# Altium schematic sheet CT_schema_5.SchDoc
size 326 x 334 mm
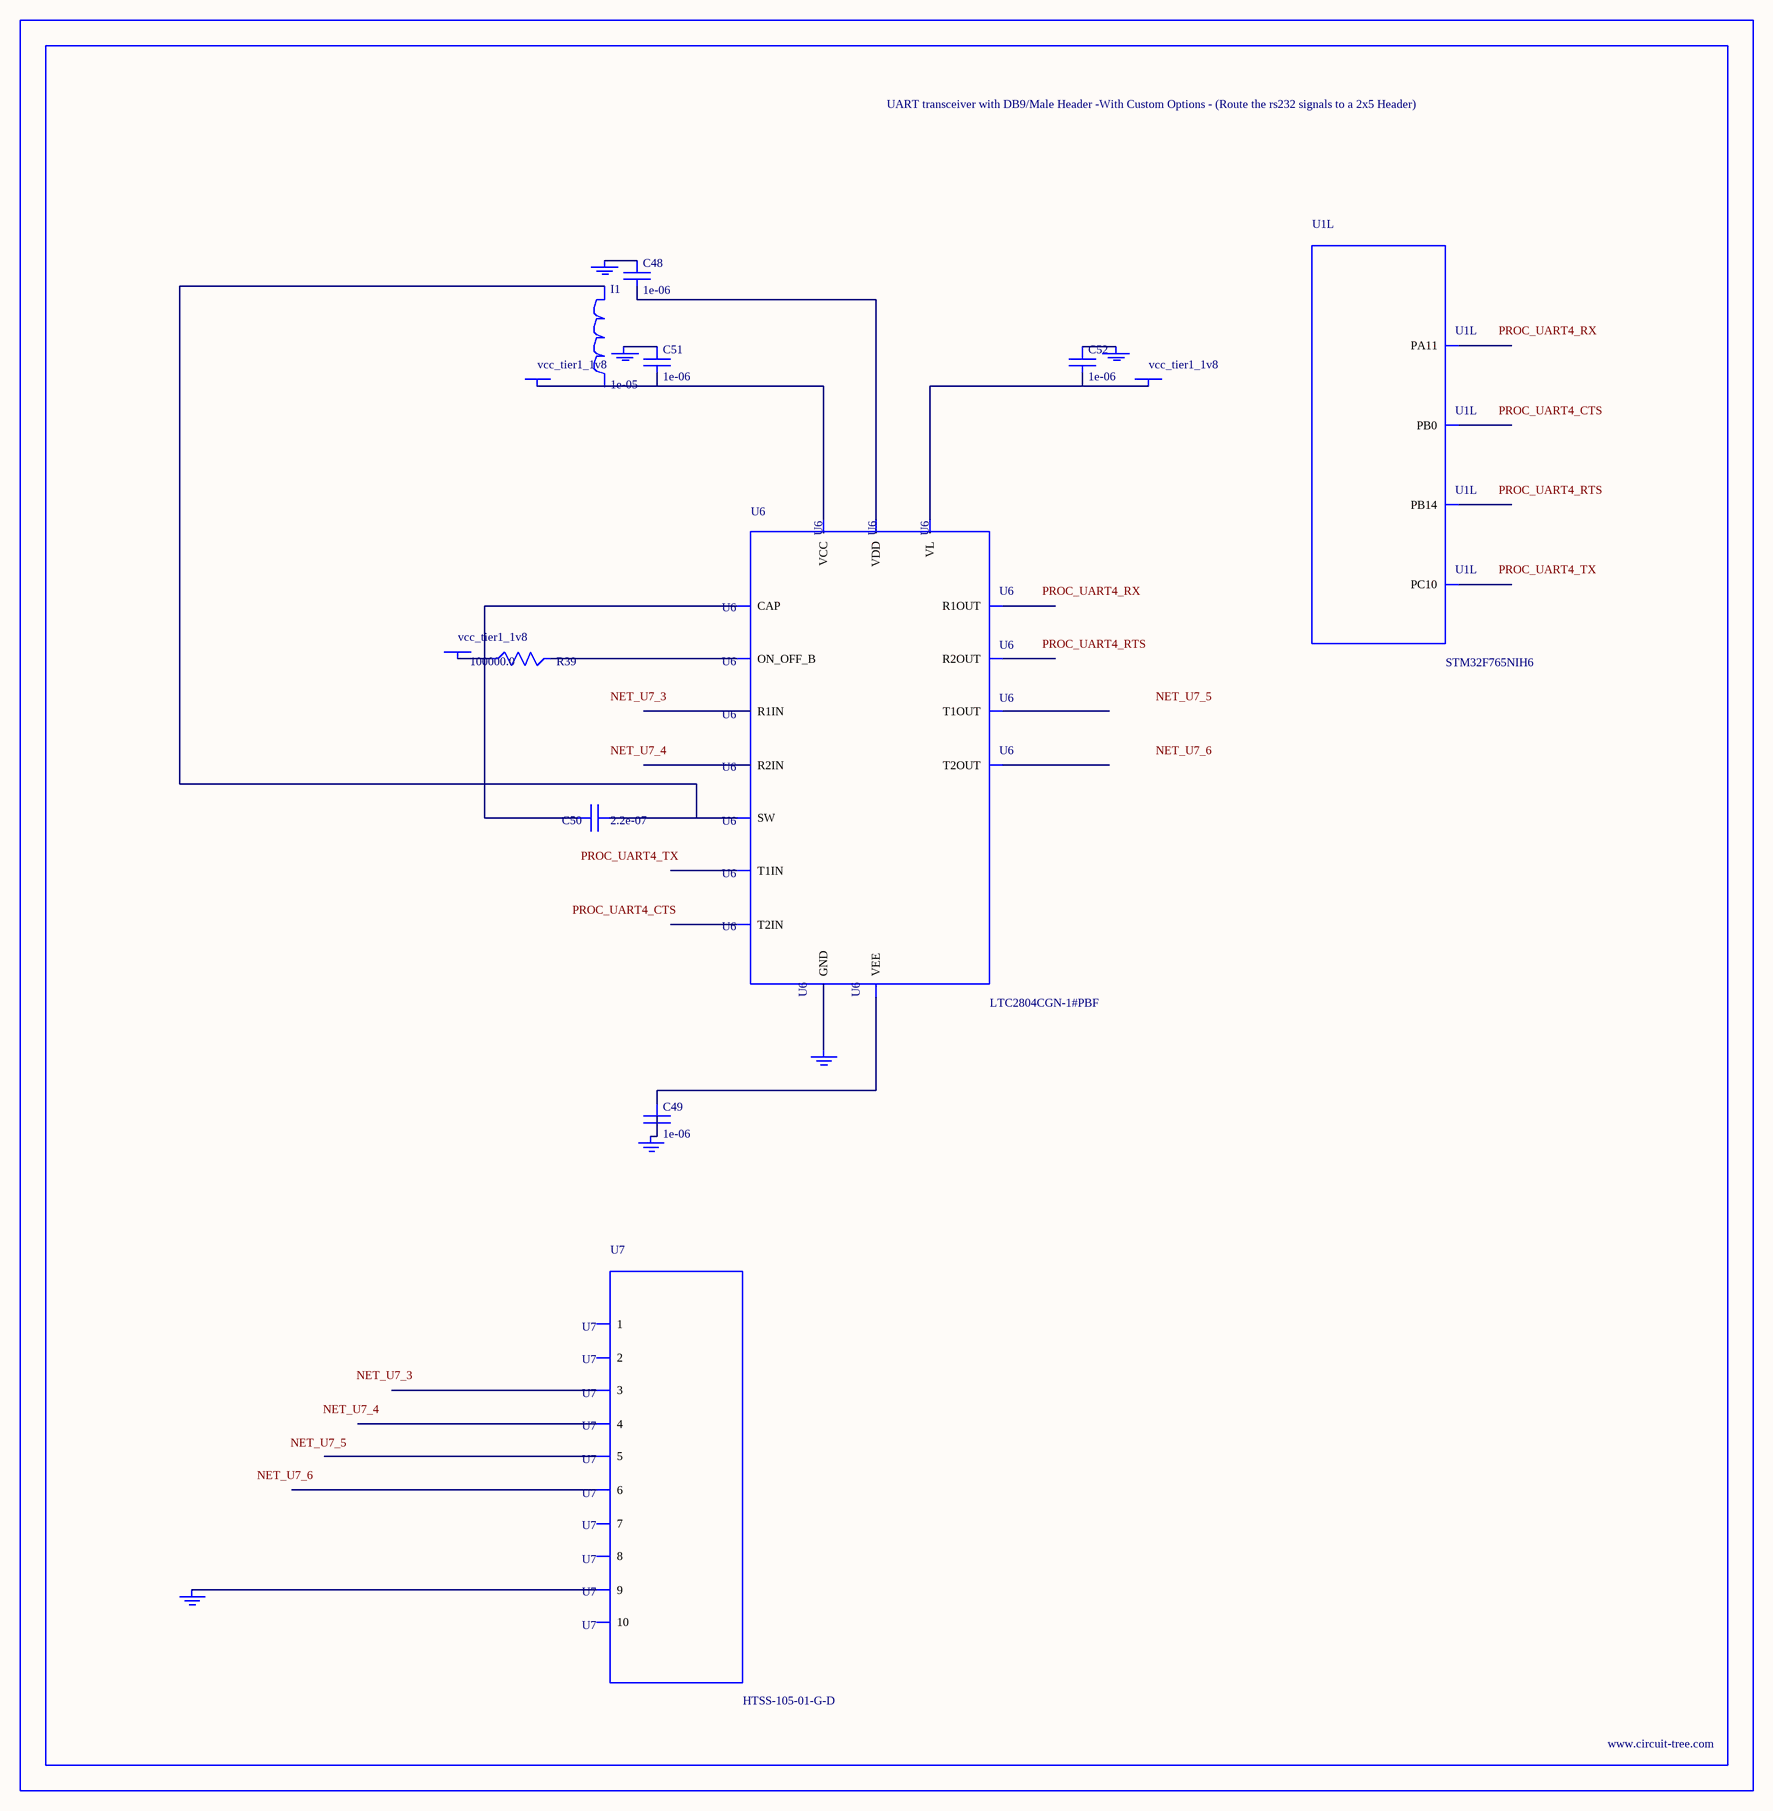
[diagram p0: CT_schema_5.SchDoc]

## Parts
BORDER4  (no value)
C48  1e-06  [C0603]
C49  1e-06  [C0603]
C50  2.2e-07  [C0603]
C51  1e-06  [C0603]
C52  1e-06  [C0603]
GND_INSTANCE_4_0  (no value)
GND_INSTANCE_4_1  (no value)
GND_INSTANCE_4_2  (no value)
GND_INSTANCE_4_3  (no value)
GND_INSTANCE_4_4  (no value)
GND_INSTANCE_4_5  (no value)
I1  1e-05  [L1210]
POWER_INSTANCE_4_0  vcc_tier1_1v8
POWER_INSTANCE_4_1  vcc_tier1_1v8
POWER_INSTANCE_4_2  vcc_tier1_1v8
R39  100000.0  [R0603]
U1  STM32F765NIH6  [TFBGA216]  (part L of 15)
U6  LTC2804CGN-1#PBF  [SSOP-16]
U7  HTSS-105-01-G-D  [HTSS-105-01-G-D]

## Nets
NetC48_1: C48.1 GND_INSTANCE_4_1.0(GND)
NetC48_2: C48.2 U6.6(VDD)
NetC49_1: C49.1 U6.9(VEE)
NetC49_2: C49.2 GND_INSTANCE_4_2.0(GND)
NetC50_1: C50.1 I1.1 U6.7(SW)
NetC50_2: C50.2 U6.10(CAP)
NetC51_1: C51.1 GND_INSTANCE_4_0.0(GND)
NetC51_2: C51.2 POWER_INSTANCE_4_0.0(PWR) U6.5(VCC)
NetC52_1: C52.1 GND_INSTANCE_4_3.0(GND)
NetC52_2: C52.2 POWER_INSTANCE_4_2.0(PWR) U6.12(VL)
NetGND_INSTANCE_4_4_0: GND_INSTANCE_4_4.0(GND) U6.8(GND)
NetGND_INSTANCE_4_5_0: GND_INSTANCE_4_5.0(GND) U7.9
NetPOWER_INSTANCE_4_1_0: POWER_INSTANCE_4_1.0(PWR) R39.1
NetR39_2: R39.2 U6.11(ON_OFF_B)

Not connected (* = marked no-connect by the designer): I1 2; U1 B14(PC10) C15(PA11) R5(PB0) R14(PB14); U6 1(R1IN) 2(R2IN) 3(T1OUT) 4(T2OUT) 13(T2IN) 14(T1IN) 15(R2OUT) 16(R1OUT); U7 1 2 3 4 5 6 7 8 10

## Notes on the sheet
- Labels drawn without touching a wire or pin: NET_U7_3, NET_U7_4, NET_U7_5, NET_U7_6, PROC_UART4_CTS, PROC_UART4_RTS, PROC_UART4_RX, PROC_UART4_TX

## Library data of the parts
BORDER4 = BORDER_PAGE4
C48 C49 C51 C52 = C0603C105K3RACTU
C50 = C0603C224K3RAC
GND_INSTANCE_4_0-GND_INSTANCE_4_5 = GND
I1 = CBC3225T100MR
POWER_INSTANCE_4_0-POWER_INSTANCE_4_2 = PWR
R39 = RC0603JR-07100KL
